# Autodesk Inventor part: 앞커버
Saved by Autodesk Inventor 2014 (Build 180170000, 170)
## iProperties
Created: 2024-08
Part Number: 앞커버
Material: 일반
Document SubType Name: Modeling
Designer: dg
Density: 1 g/cm^3
Appearance: 기본값
Author: dg
Author: jhkim
Creation Date: 2024-08-09
Sending System: Autodesk Inventor 2025
Preprocessor: ST-DEVELOPER v20
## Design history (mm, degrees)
node "앞커버1"
node "솔리드1"
node "기준1"
